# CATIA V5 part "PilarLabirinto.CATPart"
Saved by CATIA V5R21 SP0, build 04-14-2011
Part number: PilarLabirinto
Bounding box of the stored display mesh (mm): x 0 to 5, y 0 to 5, z 0 to 50
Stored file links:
  C:\Users\fisic\Desktop\labirinto catia\PilarLabirinto.CATPart
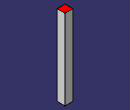
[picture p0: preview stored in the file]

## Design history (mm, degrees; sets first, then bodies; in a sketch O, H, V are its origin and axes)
Body1 (main body)
  Sketch1 on xy-plane, origin (0, 0, 0), H (1, 0, 0), V (0, 1, 0)
    line L1 (0, 0) -> (5, 0)
    line L2 (5, 0) -> (5, 5)
    line L3 (5, 5) -> (0, 5)
    line L4 (0, 5) -> (0, 0)
    point P2 (5, 5)
    distance P2 V = 5
    distance P2 H = 5
    horizontal: L1 H, L3 H
    vertical: L2 V, L4 V
  Pad1: profile Sketch1, direction (0, 0, 1), length 50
